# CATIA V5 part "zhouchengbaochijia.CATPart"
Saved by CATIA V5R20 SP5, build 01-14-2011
Part number: 轴承保持架
Bounding box of the stored display mesh (mm): x -100 to 100, y -99.999 to 99.999, z -2.5 to 19.843
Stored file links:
  E:\画图\zhouchengbaochijia.CATPart
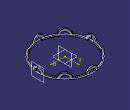
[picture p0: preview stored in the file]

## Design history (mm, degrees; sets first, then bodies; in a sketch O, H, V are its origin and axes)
Body1 (main body)
  Sketch1 on xy-plane, origin (0, 0, 0), H (1, 0, 0), V (0, 1, 0)
    circle A1 centre (0, 0) radius 100
    radius A1 = 100
  Pad1: profile Sketch1, direction (0, 0, 1), length 2.5, mirrored extent, thin wall 5
  Body2
    Sketch2 on xy-plane, origin (0, 0, 0), H (1, 0, 0), V (0, 1, 0)
      axis line L1 (97.5, 71.8838) -> (97.5, -59.2848)
      arc A1 centre (97.5, 0) radius 20 from (97.5, -20) to (97.5, 20) ccw
      point P3 (97.5, 0)
      point P4 (97.5, 20)
      point P5 (97.5, -20)
      distance V L1 = 97.5
      radius A1 = 20
      vertical: L1 V
      coincidence: P3 L1, P3 H, L1 P4, L1 P5
    Sketch3 on xy-plane, origin (0, 0, 0), H (1, 0, 0), V (0, 1, 0)
    Shaft1: profile Sketch2, axis Sketch2.L1, angle 360
    CircPattern1: of Shaft1, instances 8, angular step 45, axis from end face of Pad1
    Sketch4 on xy-plane, origin (0, 0, 0), H (1, 0, 0), V (0, 1, 0)
      circle A1 centre (0, 0) radius 95
      radius A1 = 95
    Pocket1: profile Sketch4, direction (0, 0, -1), length 60, mirrored extent
    Split1: SplitPlane start face of Pad1
    Sketch5 on xy-plane, origin (0, 0, 0), H (1, 0, 0), V (0, 1, 0)
      circle A1 centre (0, 0) radius 100
      radius A1 = 100
    Pocket2: profile Sketch5, direction (0, 0, -1), length 60, mirrored extent, outer side
  Assemble1: tool Body2
  Body3
    Plane1: type Offset, RefPlane yz-plane, Offset 97.5
    Sketch6 on Plane1, origin (97.5, 0, 0), H (0, 1, 0), V (0, 0, 1)
      axis line L1 (-24.1297, 0) -> (22.5791, 0)
      point P1 (-24.1297, 0)
      arc A1 centre (0, 0) radius 12 from (-12, 0) to (12, 0) ccw
      point P3 (-12, 0)
      point P4 (12, 0)
      radius A1 = 12
      coincidence: P1 H, L1 P4, L1 P3
      horizontal: L1 H
    Shaft2: profile Sketch6, axis Sketch6.L1, angle 360
    CircPattern2: of Shaft2, instances 8, angular step 45, axis from face of Pad1
  Remove1: tool Body3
